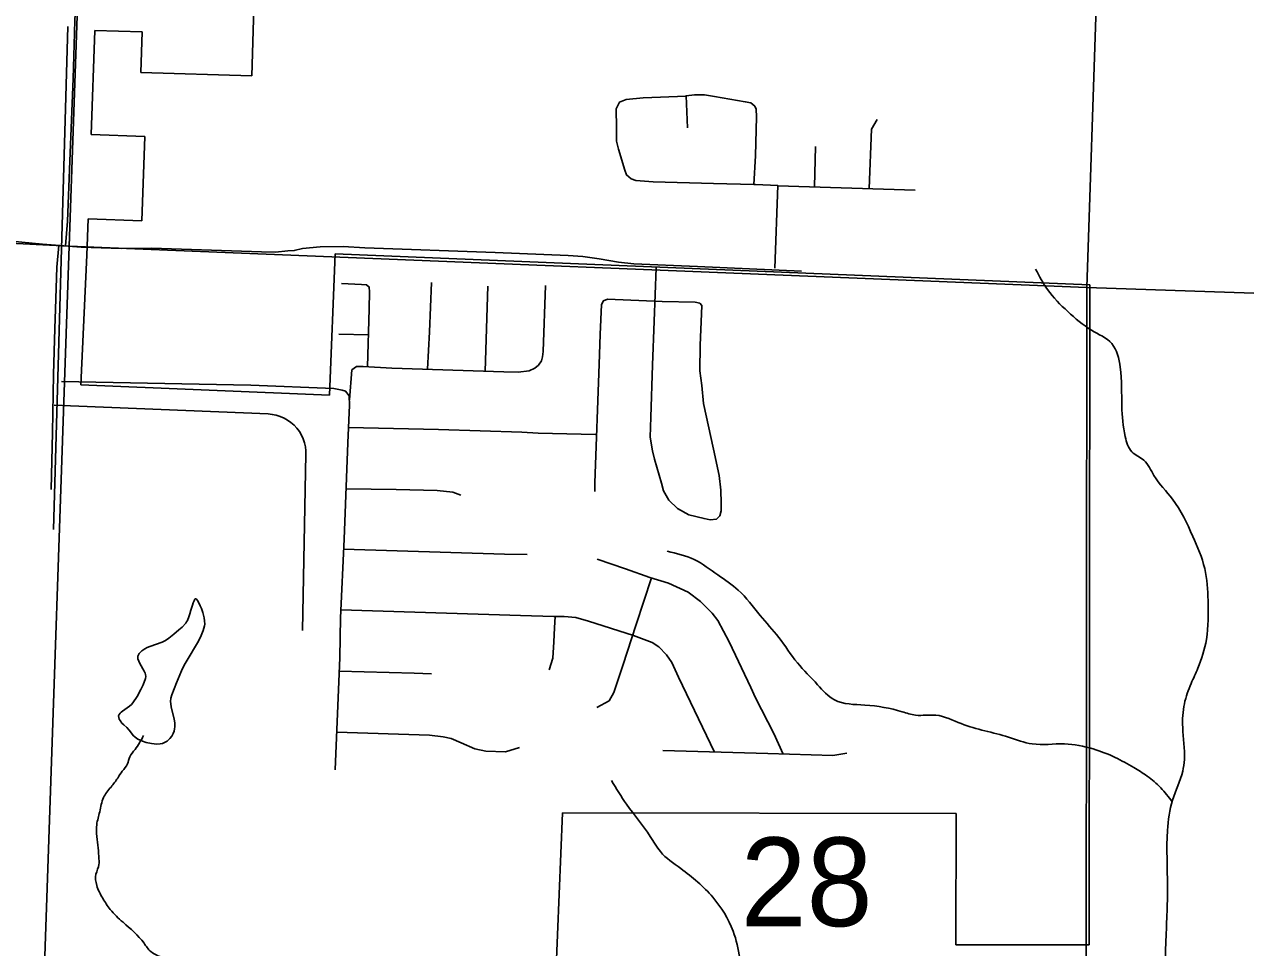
# Model space of a CAD drawing. Extents: x 1219626 to 1426462, y 456797 to 752399.
# Drawn here: x 1321124 to 1327316, y 633956 to 638638 of the extents above; entities that cross this region are included whole.
import ezdxf

# ---------------------------------------------------------------- set-up
doc = ezdxf.new("R2010")
doc.units = 0
for name, color, linetype in [('Cities Incorporated Area', 7, 'Continuous'), ('City Streets', 7, 'Continuous'), ('Lakes and Ponds', 7, 'Continuous'), ('Local Roads Improved', 7, 'Continuous'), ('Local Roads Paved', 7, 'Continuous'), ('Narrow River Creek and Branch and Slough', 7, 'Continuous'), ('Section Lines', 7, 'Continuous'), ('Section Numbers', 7, 'Continuous')]:
    doc.layers.add(name, color=color, linetype=linetype)

msp = doc.modelspace()

# ---------------------------------------------------------------- linework, layer by layer
at = {"layer": 'Cities Incorporated Area'}
for p, q in [((1322328.2, 640069), (1322276.4, 638377.3)), ((1321481.4, 638608), (1321462.1, 638080.6)), ((1321720.8, 638600.7), (1321481.4, 638608)), ((1321714.5, 638394.5), (1321720.8, 638600.7)), ((1322276.4, 638377.3), (1321714.5, 638394.5)), ((1321462.1, 638080.6), (1321734.8, 638070.6)), ((1321734.8, 638070.6), (1321719.2, 637642.7)), ((1321446.5, 637652.7), (1321439.8, 637468.7)), ((1321719.2, 637642.7), (1321446.5, 637652.7)), ((1321439.8, 637468.7), (1321410, 636809.8)), ((1322670, 636757.8), (1322699.2, 637473.9)), ((1322699.2, 637473.9), (1326526.4, 637317.9)), ((1326526.4, 637317.9), (1326523, 633968.8)), ((1321410, 636809.8), (1322670, 636757.8)), ((1323852.7, 634639.6), (1323752.1, 632177.1)), ((1325847.6, 634636), (1323852.7, 634639.6)), ((1325846.4, 633969.3), (1325847.6, 634636)), ((1326523, 633968.8), (1325846.4, 633969.3))]:
    msp.add_line(p, q, dxfattribs=at)
at = {"layer": 'City Streets'}
for p, q in [((1323473.5, 637310.1), (1323459.7, 636880)), ((1322718.4, 637067.4), (1322868.3, 637063.1))]:
    msp.add_line(p, q, dxfattribs=at)
for points in [[(1320007.2, 638879.6), (1320210.1, 638861.2), (1320508.9, 638842.9), (1320927.5, 638824.5), (1321279, 638810), (1321311.9, 638808.1), (1321334.1, 638803.7), (1321356.4, 638794), (1321371.8, 638778.1), (1321380.1, 638763.6), (1321383.9, 638741.3), (1321379.1, 638662.1), (1321378.6, 638594.4), (1321370.9, 638363.8), (1321353.9, 637945.1), (1321342.8, 637640.5), (1321331.6, 637515.1)], [(1324327.3, 637402.9), (1324316.6, 637133.1), (1324307.9, 636910.8), (1324299.2, 636645.8), (1324296.3, 636545.3), (1324307.9, 636474.7), (1324318.6, 636433.1), (1324354.4, 636311.3), (1324364, 636272.6), (1324391.1, 636225.2), (1324434.6, 636182.7), (1324492.6, 636150.8), (1324570, 636131.4), (1324600.9, 636125.6), (1324632.8, 636129.5), (1324650.2, 636145.9), (1324656, 636171.1), (1324657, 636210.7), (1324655.1, 636276.5), (1324647.3, 636350), (1324618.3, 636483.4), (1324567.1, 636715.4), (1324558.4, 636806.3), (1324548.7, 636881.8), (1324549.7, 637011.3), (1324556.4, 637170.9), (1324559.3, 637213.4), (1324547.7, 637224), (1324524.5, 637228.9), (1324357.3, 637232.7), (1324080.7, 637244.3), (1324059.4, 637235.6), (1324049.8, 637218.2), (1324043, 637065.5), (1324038.2, 636915.6), (1324016.9, 636312.3), (1324015.9, 636269.7)], [(1322730.9, 637324.6), (1322832.5, 637318.8), (1322858.6, 637317.8), (1322872.1, 637306.2), (1322874, 637282.1), (1322872.1, 637195), (1322863.6, 636901.8)], [(1322771.4, 636734.6), (1322784.1, 636885.6), (1322808.3, 636903), (1322841.2, 636903), (1322986.2, 636895.3), (1323554.7, 636876.9), (1323627.2, 636875), (1323682.4, 636880.8), (1323711.4, 636894.3), (1323730.7, 636910.8), (1323745.2, 636931.1), (1323750, 636952.3), (1323754.9, 636979.4), (1323766.5, 637314.9)], [(1323188.3, 637328.5), (1323178.6, 637079), (1323168.4, 636889.4)], [(1324018.8, 636558.8), (1323728.8, 636564.6), (1323646.6, 636569.4), (1323223.1, 636583), (1322767.3, 636593.8)], [(1322754.6, 636283.4), (1323009.4, 636279.4), (1323217.3, 636273.6), (1323295.6, 636265.8), (1323336.2, 636250.4)], [(1323672.7, 635949.7), (1323558.6, 635951.6), (1322742.3, 635977.2)], [(1324970.9, 634937.2), (1324923.9, 635040.8), (1324831, 635222.6), (1324806.9, 635275.7), (1324697.6, 635506.8), (1324639.6, 635615.1), (1324610.6, 635652.8), (1324552.6, 635710.8), (1324488.8, 635759.2), (1324389.2, 635803.7), (1324294.4, 635833.6), (1324171.6, 635877.1), (1324028.5, 635925.5)], [(1324302.8, 635831), (1324224.8, 635594.8), (1324158.1, 635386.9), (1324112.6, 635249.6), (1324089.4, 635208.1), (1324026.6, 635174.2)], [(1322728.8, 635668.7), (1323639.8, 635639.3), (1323809, 635635.4), (1323861.2, 635635.4), (1323920.2, 635630.6), (1323984, 635612.2), (1324212.2, 635538.7), (1324306, 635503.9), (1324339.8, 635481.7), (1324379.5, 635440.1), (1324406.6, 635402.4), (1324440.4, 635327.9), (1324541.9, 635116.2), (1324622.6, 634947.6)], [(1323783.9, 635364.7), (1323803.2, 635423.7), (1323809, 635506.8), (1323811, 635577.4), (1323814.7, 635635.4)], [(1322720.4, 635358.6), (1323099.3, 635347.3), (1323188.3, 635344.4)], [(1322707.8, 635049), (1323178.6, 635033), (1323247.3, 635024.3), (1323286.9, 635015.6), (1323338.1, 634993.4), (1323406.8, 634963.4), (1323463.8, 634952.8), (1323563.4, 634948), (1323634, 634970.2)], [(1324360.2, 634955.7), (1324893.9, 634939.3), (1325223.6, 634930.6), (1325294.2, 634942.2)]]:
    msp.add_lwpolyline(points, dxfattribs=at)
at = {"layer": 'Lakes and Ponds'}
msp.add_lwpolyline([(1321654.9, 635058), (1321677.1, 635030.4), (1321692.9, 635018), (1321699.1, 635012.2), (1321723.1, 635002.1), (1321741.2, 634996.5), (1321768.3, 634990.7), (1321795.2, 634987.8), (1321811.8, 634988.5), (1321824.2, 634991.4), (1321833.5, 634995.1), (1321847.2, 635003.4), (1321853.9, 635009), (1321860.6, 635015.6), (1321871.1, 635028.8), (1321878.3, 635041.5), (1321882.8, 635053.6), (1321885.3, 635065), (1321886.5, 635075.8), (1321885.8, 635096.3), (1321883, 635114.4), (1321868.4, 635177.4), (1321866, 635192.8), (1321865.3, 635204.2), (1321866.3, 635221), (1321870.5, 635237.3), (1321894.3, 635299.1), (1321920, 635360.1), (1321934.2, 635389), (1321948.4, 635414.1), (1322001.2, 635501), (1322012.9, 635522.7), (1322020.6, 635538.9), (1322030.2, 635563.3), (1322036.8, 635587.8), (1322037.9, 635595.9), (1322037.8, 635612.4), (1322035.7, 635627.8), (1322028.6, 635655.5), (1322021.3, 635675.7), (1322015.2, 635689.8), (1322005.9, 635708.4), (1322001.4, 635716.1), (1321997.2, 635722.4), (1321994.1, 635725.3), (1321991.2, 635725.4), (1321988.6, 635723.4), (1321986.1, 635719.9), (1321983.8, 635715.3), (1321979.4, 635704), (1321975.5, 635691.8), (1321968.3, 635667.3), (1321962.4, 635648), (1321957.7, 635634.1), (1321950.2, 635615.5), (1321946.1, 635607.9), (1321941.7, 635601.7), (1321923.4, 635581.6), (1321907.6, 635566.6), (1321882.2, 635544.9), (1321856.6, 635524.4), (1321839.2, 635513.3), (1321822.6, 635505.6), (1321760.6, 635483.7), (1321745.6, 635477.1), (1321734.8, 635471.3), (1321719.6, 635460.7), (1321706.1, 635447.2), (1321701.7, 635440.3), (1321699.5, 635433.5), (1321699, 635426.9), (1321699.7, 635420.6), (1321703.5, 635408.3), (1321708.9, 635397.3), (1321731.7, 635358), (1321736, 635348.3), (1321738.2, 635341.1), (1321739.5, 635330.6), (1321737.8, 635320.5), (1321725.2, 635288.7), (1321714.1, 635264.9), (1321695.2, 635230.1), (1321674.4, 635197.7), (1321666.1, 635188.3), (1321657, 635180.5), (1321621.3, 635155.6), (1321613.7, 635149.5), (1321608.9, 635144.9), (1321603.6, 635137.8), (1321601.2, 635130.4), (1321601.8, 635122.1), (1321604.7, 635114.3), (1321608.7, 635107.2), (1321618.4, 635094.6), (1321627.4, 635085.4), (1321642.6, 635072.3), (1321654.9, 635058)], dxfattribs=at)
at = {"layer": 'Local Roads Improved'}
for p, q in [((1321271.2, 636077), (1321344.4, 638627.3)), ((1321275.1, 636706.6), (1322359.6, 636662.5)), ((1322551.5, 636458.8), (1322534.4, 635564.1))]:
    msp.add_line(p, q, dxfattribs=at)
msp.add_lwpolyline([(1322359.6, 636662.5), (1322380.5, 636660.5), (1322401, 636656.4), (1322421, 636650.2), (1322440.2, 636641.9), (1322458.5, 636631.6), (1322475.5, 636619.5), (1322491.3, 636605.7), (1322505.4, 636590.3), (1322517.9, 636573.5), (1322528.6, 636555.5), (1322537.4, 636536.5), (1322544.1, 636516.7), (1322548.7, 636496.2), (1322551.1, 636475.4), (1322551.5, 636458.8)], dxfattribs=at)
at = {"layer": 'Local Roads Paved'}
for p, q in [((1325129.2, 637814.3), (1325135.6, 638018.3)), ((1324943.1, 637820.3), (1325640.3, 637797.9))]:
    msp.add_line(p, q, dxfattribs=at)
for points in [[(1324479.2, 638274.6), (1324260.6, 638265.9), (1324174.5, 638257.2), (1324141.6, 638244.6), (1324124.2, 638210.8), (1324126.2, 638113.1), (1324126.2, 638046.4), (1324136.8, 638005.8), (1324168.7, 637899.4), (1324177.4, 637875.2), (1324200.6, 637855.9), (1324223.8, 637846.2), (1324311.8, 637840.4), (1324617.3, 637831.7), (1324822.3, 637826.9)], [(1324928.7, 637401.5), (1324943.2, 637822.1), (1324830.1, 637826.9), (1324822.3, 637826.9), (1324831, 637971.9), (1324835.9, 638170.1), (1324833.9, 638207.9), (1324827.2, 638224.3), (1324806.9, 638240.7), (1324778.8, 638246.5), (1324622.2, 638272.6), (1324572.9, 638280.4), (1324520.7, 638280.4), (1324479.1, 638276.5), (1324485.9, 638113.1)], [(1325407.7, 637805.4), (1325418.9, 638107.3), (1325447.9, 638155.6)], [(1325064.1, 637386), (1324536.1, 637410.2), (1324213.2, 637424.7), (1324136.8, 637432.4), (1324038.2, 637448.8), (1323955, 637460.4), (1323880.6, 637466.2), (1323511.2, 637480.7), (1322849.9, 637504.9), (1322739.6, 637511.7), (1322622.6, 637510.7), (1322534.6, 637501.1), (1322492.1, 637491.4), (1322460.2, 637489.5), (1322397.3, 637483.6), (1322325.8, 637484.6), (1321767.9, 637503), (1321615.1, 637501.1), (1321411.1, 637508.8), (1321215.8, 637524.3), (1321059.2, 637538.8)], [(1321298.8, 637517.7), (1321287.7, 637407.5), (1321281.4, 637193.8), (1321278, 637096.2), (1321271.8, 636862.2), (1321265.5, 636568.7), (1321258.7, 636278.7)], [(1322700, 634857.1), (1322723.2, 635427.5), (1322727.1, 635628.7), (1322744.5, 636027), (1322763.8, 636516.3), (1322772.5, 636707.7), (1322770.6, 636755.1), (1322752.2, 636778.3), (1322734.8, 636783.1), (1322693.2, 636790.9), (1322271.7, 636809.2), (1321311.5, 636827.6)]]:
    msp.add_lwpolyline(points, dxfattribs=at)
at = {"layer": 'Narrow River Creek and Branch and Slough'}
for points in [[(1324055.1, 638887.8), (1324123.7, 638999.2), (1324218, 639093.5), (1324355.1, 639256.5), (1324440.8, 639350.8), (1324526.5, 639436.5), (1324612.2, 639470.8), (1324715, 639470.8), (1324929.3, 639462.3), (1325074.9, 639453.7), (1325246.3, 639479.4), (1325434.9, 639548), (1325640.6, 639599.4), (1325777.7, 639625.2), (1325914.8, 639659.5), (1326129, 639650.9), (1326283.3, 639599.4), (1326463.2, 639556.6), (1326548.9, 639505.1), (1326643.2, 639436.5), (1326711.8, 639350.8), (1326806, 639265), (1326926, 639213.6), (1327097.4, 639179.3), (1327354.5, 639127.8), (1327534.5, 639110.7), (1327688.7, 639102.1), (1327783, 639050.7), (1327860.1, 638990.7), (1327937.2, 638913.5), (1328134.3, 638793.4), (1328280, 638707.7), (1328494.3, 638587.7), (1328717.1, 638476.2), (1328905.6, 638390.4), (1329188.4, 638313.3), (1329282.7, 638330.4), (1329411.2, 638381.9), (1329582.6, 638390.4), (1329754, 638321.9), (1329891.1, 638219), (1330118.3, 638021.7), (1330229.7, 637910.3), (1330358.2, 637798.8), (1330495.3, 637738.8), (1330649.6, 637653), (1330821, 637550.2), (1330906.7, 637464.4), (1330992.4, 637344.4), (1331095.2, 637207.2), (1331172.3, 637087.1), (1331206.6, 636992.8), (1331283.7, 636872.8), (1331378, 636761.3), (1331438, 636658.4), (1331489.4, 636555.5), (1331523.7, 636478.3), (1331532.3, 636418.3), (1331540.8, 636332.6), (1331566.5, 636204), (1331626.5, 636092.5), (1331763.6, 635989.6), (1331969.3, 635912.4)], [(1326251.2, 637396.4), (1326311.1, 637293.5), (1326414, 637182), (1326534, 637087.7), (1326636.8, 637019.1), (1326679.6, 636899.1), (1326688.2, 636701.9), (1326705.3, 636547.5), (1326739.6, 636470.4), (1326799.6, 636427.5), (1326851, 636350.3), (1326945.3, 636230.3), (1327048.1, 636041.6), (1327108.1, 635878.7), (1327125.3, 635715.8), (1327116.7, 635518.6), (1327073.8, 635372.8), (1327039.6, 635295.7), (1327005.3, 635192.8), (1326996.7, 635072.7), (1327005.3, 634909.8), (1326996.7, 634849.8), (1326945.3, 634704), (1326919.6, 634549.7), (1326919.6, 634266.7), (1326911, 633975.2), (1326902.5, 633769.4), (1326885.3, 633623.6), (1326868.2, 633477.9), (1326868.2, 633409.3), (1326825.3, 633340.7), (1326816.8, 633229.2), (1326868.2, 633100.6), (1327005.3, 632898.3), (1327065.3, 632752.5), (1327125.3, 632435.3), (1327193.8, 632118), (1327219.5, 631877.9), (1327202.4, 631620.7), (1327151, 631423.5), (1327099.6, 631303.5), (1326851, 631080.5), (1326731.1, 630994.8), (1326585.4, 630874.7), (1326474, 630729), (1326379.7, 630660.4), (1326336.8, 630617.5), (1326272.4, 630628.1)], [(1324382.9, 635966.3), (1324520.1, 635923.4), (1324640, 635846.2), (1324742.9, 635769.1), (1324854.3, 635640.5), (1324948.5, 635529), (1325042.8, 635400.4), (1325145.7, 635288.9), (1325231.4, 635211.7), (1325385.6, 635186), (1325574.1, 635151.7), (1325642.7, 635134.6), (1325745.5, 635134.6), (1325874.1, 635091.7), (1326114, 635023.1), (1326234, 634988.8), (1326396.8, 634988.8), (1326542.5, 634963.1), (1326653.9, 634920.2), (1326748.2, 634868.8), (1326816.8, 634825.9), (1326885.3, 634765.9), (1326943.2, 634695.7)], [(1321728.4, 635030.7), (1321684.8, 634960.7), (1321658.1, 634922.6), (1321646.7, 634888.3), (1321620, 634850.1), (1321597.1, 634815.8), (1321562.9, 634770.1), (1321524.8, 634716.8), (1321505.7, 634644.4), (1321490.5, 634579.6), (1321490.5, 634518.6), (1321498.1, 634461.4), (1321501.9, 634404.3), (1321501.9, 634377.6), (1321486.7, 634328.1), (1321490.5, 634270.9), (1321521, 634206.1), (1321559.1, 634148.9), (1321623.8, 634084.2), (1321730.5, 633977.5), (1321764.7, 633935.5), (1321840.9, 633897.4), (1321901.9, 633863.1), (1321970.4, 633832.6), (1322023.7, 633794.5), (1322099.9, 633714.5), (1322164.7, 633638.3), (1322202.7, 633569.7), (1322248.4, 633504.9), (1322290.3, 633447.7), (1322377.9, 633360.1), (1322412.2, 633333.4), (1322499.8, 633318.2), (1322648.4, 633302.9), (1322747.4, 633287.7), (1322823.6, 633264.8), (1322859.4, 633230.3), (1322878.4, 633157.9), (1322927.9, 633081.6), (1322988.9, 633013), (1323042.2, 632921.6), (1323076.5, 632830.1), (1323137.4, 632704.4), (1323183.1, 632582.4), (1323217.4, 632506.2), (1323266.9, 632433.8), (1323331.7, 632361.4), (1323430.7, 632258.5), (1323529.7, 632182.3), (1323609.7, 632136.5), (1323682.1, 632079.4), (1323731.6, 632048.9), (1323781.1, 631972.7), (1323845.9, 631926.9), (1323963.9, 631888.8), (1324059.1, 631869.8), (1324146.7, 631869.8), (1324222.9, 631862.2), (1324360, 631820.2), (1324459.1, 631782.1), (1324569.5, 631766.9), (1324699, 631766.9), (1324870.4, 631759.3), (1325007.5, 631759.3), (1325133.2, 631751.6), (1325228.4, 631717.3), (1325297, 631667.8), (1325392.2, 631618.3), (1325457, 631587.8), (1325529.3, 631584), (1325571.2, 631568.7), (1325712.9, 631518.2), (1325754.8, 631480.1), (1325895.7, 631331.4), (1325960.5, 631262.8), (1326086.2, 631156.1), (1326185.2, 631041.8), (1326257.6, 630946.5), (1326299.5, 630855.1), (1326322.3, 630729.3), (1326288, 630653.1), (1326238.5, 630580.7), (1326173.8, 630504.5), (1326128.1, 630451.1), (1326116.7, 630386.4), (1326116.7, 630310.1), (1326150.9, 630253), (1326208.1, 630176.8), (1326234.7, 630134.8), (1326250, 630066.2), (1326280.4, 630009.1)], [(1325548, 631577.2), (1325479.9, 631664.1), (1325377, 631724.2), (1325317, 631809.9), (1325231.4, 631990), (1325222.8, 632075.7), (1325274.2, 632230.1), (1325299.9, 632393), (1325308.5, 632555.9), (1325325.6, 632684.5), (1325308.5, 632890.3), (1325308.5, 633010.3), (1325248.5, 633130.4), (1325077.1, 633293.3), (1324965.7, 633361.9), (1324862.9, 633464.8), (1324802.9, 633593.4), (1324751.4, 633902.1), (1324717.2, 634039.3), (1324614.3, 634210.8), (1324451.5, 634356.5), (1324348.7, 634442.3), (1324297.2, 634519.4), (1324177.3, 634682.3), (1324100.1, 634802.4)]]:
    msp.add_spline(points, degree=3, dxfattribs=at)
at = {"layer": 'Section Lines'}
for p, q in [((1321350.2, 637513.8), (1321531.5, 642738.6)), ((1326684.8, 642567.4), (1326511.4, 637303.6)), ((1321350.2, 637513.8), (1316109.8, 637770.5)), ((1321172.4, 632281.9), (1321350.2, 637513.8)), ((1326511.4, 637303.6), (1321350.2, 637513.8)), ((1326511.4, 637303.6), (1326506.1, 632065.2)), ((1331751.6, 637130.9), (1326511.4, 637303.6))]:
    msp.add_line(p, q, dxfattribs=at)

# ---------------------------------------------------------------- texts
at = {"layer": 'Section Numbers'}
msp.add_text('28', height=450, rotation=359.99988, dxfattribs=at).set_placement((1324755.2, 634064.2))

doc.saveas('drawing.dxf')
